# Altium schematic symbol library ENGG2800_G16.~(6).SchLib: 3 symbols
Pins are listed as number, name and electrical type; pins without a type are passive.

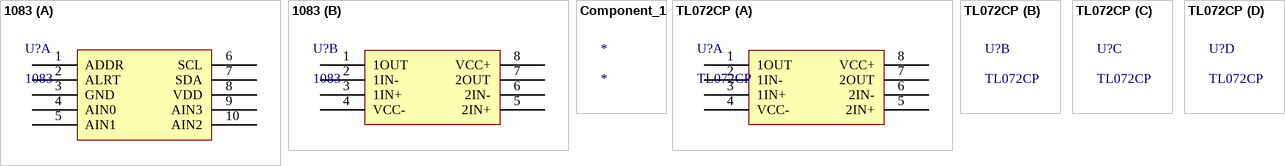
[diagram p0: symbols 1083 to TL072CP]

## 1083
designator U?
EVAL BOARD ADS1115 16-BIT ADC; Manufacturer: Adafruit Industries; Description: EVAL BOARD ADS1015 12-BIT ADC; Number of Bits: 12; Evaluation Kit: Yes; Number of A/D Converters: 1; Sampling Rate: 3300S/s; Interface: I2C,Serial
part A pins: 1 ADDR, 2 ALRT, 3 GND, 4 AIN0, 5 AIN1, 6 SCL, 7 SDA, 8 VDD, 9 AIN3, 10 AIN2
part B pins: 1 1OUT, 2 1IN-, 3 1IN+, 4 VCC-, 5 2IN+, 6 2IN-, 7 2OUT, 8 VCC+

## Component_1
designator *

## TL072CP
designator U?
IC, OP AMP, DUAL JFET, DIP8; Bandwidth:3MHz; No. of Amplifiers:2; Slew Rate:13V/ s; Supply Voltage Range:7V to 36V; Amplifier Case Style:DIP; No. of Pins:8; Operating Temperature Min:0 C; Operating Temperature Max:70 C; ;RoHS Compliant: Yes; Manufacturer: Texas Instruments; Bandwidth: 3MHz; Number of Channels: 2; Voltage Gain: 106.02dB; Nominal Supply Current: 5mA; Max Supply Voltage: 18V; Min Dual Supply Voltage: 3.5V; Dual Supply Voltage: 9V; Common Mode Rejection Ratio: 70dB; Slew Rate: 13V/µs; Max I/O Voltage: 10mV; Input Bias Current: 200pA; Input Offset Voltage (Vos): 3mV; Operating Supply Current: 1.4mA
part A pins: 1 1OUT, 2 1IN-, 3 1IN+, 4 VCC-, 5 2IN+, 6 2IN-, 7 2OUT, 8 VCC+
